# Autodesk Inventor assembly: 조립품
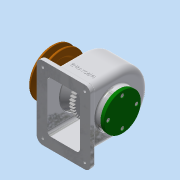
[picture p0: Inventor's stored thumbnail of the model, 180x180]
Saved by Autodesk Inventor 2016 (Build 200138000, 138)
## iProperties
Created: 2018-11
Part Number: 조립품
Material: 일반
Document SubType Name: Assembly
Designer: 공506_41
Author: 공506_41
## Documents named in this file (14)
- C:\Users\공506_41\Desktop\새 폴더 (2)\481111V1011\조립품.iam
- C:\Users\공506_41\Desktop\새 폴더 (2)\481111V1011\축.ipt
- C:\Users\공506_41\Desktop\새 폴더 (2)\481111V1011\키 5x5x18.ipt
- C:\Users\공506_41\Desktop\새 폴더 (2)\481111V1011\키 6x6x22.ipt
- C:\Users\공506_41\Desktop\새 폴더 (2)\481111V1011\V-벨트풀리.ipt
- C:\Users\공506_41\Desktop\새 폴더 (2)\481111V1011\뒤커버.ipt
- C:\Users\공506_41\Desktop\새 폴더 (2)\481111V1011\멈춤나사 M4.ipt
- C:\Users\공506_41\Desktop\새 폴더 (2)\481111V1011\베어링 6203.ipt
- C:\Users\공506_41\Desktop\새 폴더 (2)\481111V1011\본체.ipt
- C:\Users\공506_41\Desktop\새 폴더 (2)\481111V1011\볼트 M4.ipt
- C:\Users\공506_41\Desktop\새 폴더 (2)\481111V1011\부시.ipt
- C:\Users\공506_41\Desktop\새 폴더 (2)\481111V1011\스퍼기어.ipt
- C:\Users\공506_41\Desktop\새 폴더 (2)\481111V1011\앞커버.ipt
- C:\Users\공506_41\Desktop\새 폴더 (2)\481111V1011\오일 실 28 40 8.ipt
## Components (1 placed, 1 different names)
1. V-벨트풀리:1
